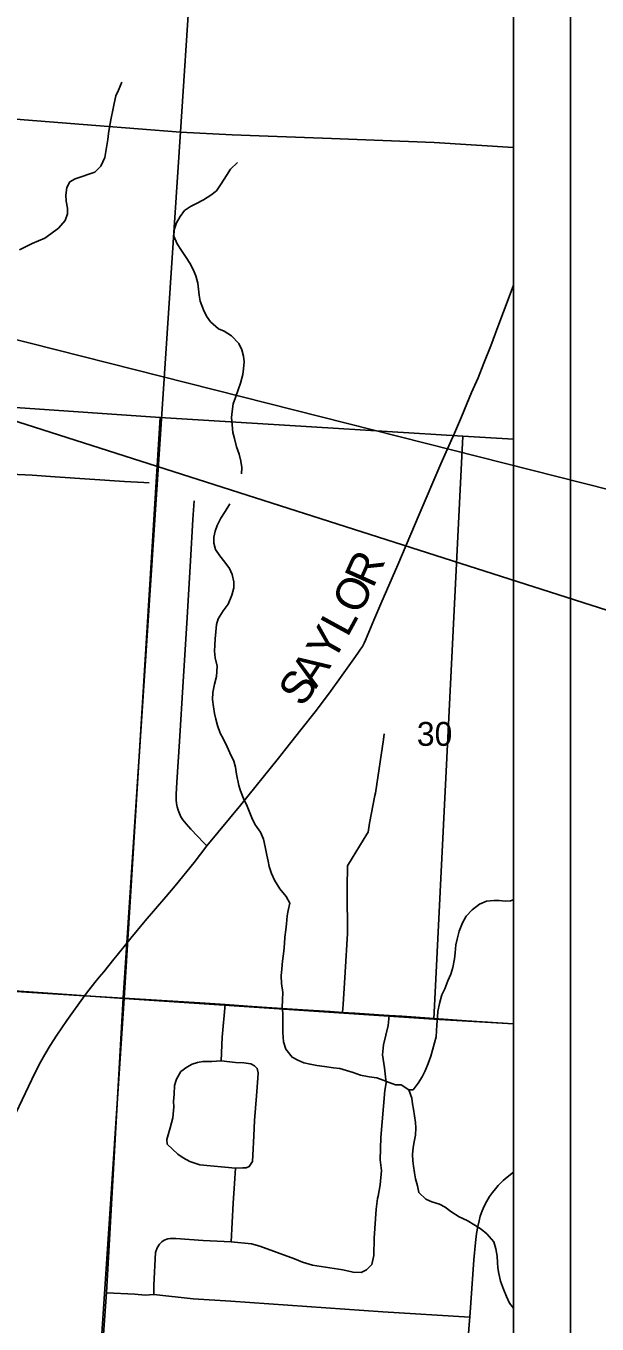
# Model space of a CAD drawing. Extents: x 0 to 34, y 0 to 22.
# Drawn here: x 8.044 to 9.046, y 15.327 to 17.603 of the extents above; entities that cross this region are included whole.
import ezdxf

# ---------------------------------------------------------------- set-up
doc = ezdxf.new("R2010")
doc.units = 0
for name, color, linetype in [('GM_X_Corporation', 7, 'Continuous'), ('GM_X_County_Road', 7, 'Continuous'), ('GM_X_Minor_River', 7, 'Continuous'), ('GM_X_Section_Text', 7, 'Continuous'), ('GM_X_State_Route', 7, 'Continuous'), ('GM_X_Township_Road', 7, 'Continuous'), ('GM_X_Township_Road_Text', 7, 'Continuous'), ('SH_Data', 7, 'Continuous'), ('SH_Text', 7, 'Continuous')]:
    doc.layers.add(name, color=color, linetype=linetype)

msp = doc.modelspace()

# ---------------------------------------------------------------- linework, layer by layer
at = {"layer": 'GM_X_Corporation'}
for points in [[(3.0167, 14.1), (8.9, 14.1), (8.9, 17.9001), (8.3494, 17.9349), (8.1742, 17.9461), (7.8447, 17.9665), (7.5344, 17.9901), (7.2487, 18.0119), (6.5673, 18.064), (6.0904, 18.0983)], [(3.0167, 14.1), (8.1011, 14.1), (8.1079, 14.1976), (8.1194, 14.3701), (8.12, 14.3767), (8.1177, 14.3813), (8.1477, 14.8503), (8.1489, 14.8684), (8.1501, 14.8865), (8.1855, 15.3822), (8.215, 15.8988), (8.2214, 15.9952), (8.3153, 17.4178), (8.3494, 17.9349), (8.1742, 17.9461), (7.8447, 17.9665), (7.5344, 17.9901), (7.2487, 18.0119), (6.5673, 18.064), (6.0904, 18.0983)], [(3.0169, 14.1), (8.9, 14.1), (8.9, 17.8995), (8.3496, 17.9344), (8.1744, 17.9455), (7.8449, 17.9659), (7.5346, 17.9896), (7.2489, 18.0114), (6.5646, 18.0583), (6.0906, 18.0978)]]:
    msp.add_lwpolyline(points, dxfattribs=at)
for points in [[(8.1011, 14.1), (8.9, 14.1), (8.9, 17.9001), (8.3494, 17.9349), (8.3153, 17.4178), (8.2214, 15.9952), (8.215, 15.8988), (8.1855, 15.3822), (8.1501, 14.8865), (8.1489, 14.8684), (8.1477, 14.8503), (8.1177, 14.3813), (8.12, 14.3767), (8.1194, 14.3701), (8.1079, 14.1976)], [(7.7715, 16.9516), (8.2797, 16.9169), (8.2166, 15.8976), (7.7055, 15.9334)], [(8.2797, 16.9169), (8.811, 16.8838), (8.7597, 15.8616), (8.2166, 15.8976)], [(8.9, 15.8531), (8.9, 16.8787), (8.811, 16.8838), (8.7597, 15.8616)], [(7.2018, 15.9686), (7.7055, 15.9334), (8.2166, 15.8976), (8.1497, 14.8881), (7.1441, 14.9641)], [(8.9, 14.8153), (8.9, 15.8531), (8.7597, 15.8616), (8.2166, 15.8976), (8.1497, 14.8881), (8.1482, 14.8695)]]:
    msp.add_lwpolyline(points, close=True, dxfattribs=at)
at = {"layer": 'GM_X_County_Road'}
for points in [[(6.5533, 16.0128), (6.5873, 16.0106), (7.3781, 15.9549), (7.4292, 15.951), (7.4581, 15.95), (7.5317, 15.9445), (7.5902, 15.9401), (7.7101, 15.9317), (7.717, 15.9313), (7.7697, 15.9277), (7.8593, 15.9217), (7.9306, 15.9171), (7.9832, 15.9128), (8.0451, 15.9087), (8.1468, 15.9026)], [(8.1468, 15.9026), (8.2152, 15.8983), (8.2261, 15.8976)], [(8.2261, 15.8976), (8.3589, 15.8893), (8.394, 15.887), (8.4333, 15.8844), (8.4581, 15.8826), (8.5293, 15.8777), (8.5781, 15.8746), (8.5998, 15.8732), (8.6214, 15.8718), (8.6725, 15.8685), (8.6816, 15.8679), (8.7037, 15.8664), (8.8175, 15.8587), (8.9, 15.8531)], [(8.819, 15.2872), (8.8226, 15.3327), (8.823, 15.3387), (8.8304, 15.439), (8.8332, 15.4699), (8.8351, 15.4854), (8.8371, 15.4977), (8.8393, 15.5076), (8.8415, 15.516), (8.8448, 15.5252), (8.8483, 15.5335), (8.8527, 15.5419), (8.8577, 15.5501), (8.8629, 15.5576), (8.868, 15.5641), (8.8727, 15.5696), (8.877, 15.574), (8.8817, 15.5784), (8.8888, 15.5845), (8.9, 15.5929)]]:
    msp.add_lwpolyline(points, dxfattribs=at)
at = {"layer": 'GM_X_Minor_River'}
for points in [[(8.1431, 17.3395), (8.1545, 17.3432), (8.1652, 17.3472), (8.1759, 17.3577), (8.1825, 17.3725), (8.1849, 17.3869), (8.1878, 17.4043), (8.189, 17.4149), (8.1918, 17.4297), (8.1938, 17.4414), (8.1966, 17.4558), (8.1994, 17.4676), (8.2022, 17.4808), (8.2065, 17.491), (8.2123, 17.505)], [(8.4157, 17.364), (8.4035, 17.3523), (8.3962, 17.3414), (8.3869, 17.3263), (8.3785, 17.3143), (8.3689, 17.3068), (8.3556, 17.2982), (8.3434, 17.2918), (8.3331, 17.287), (8.3228, 17.2795), (8.3151, 17.269), (8.3082, 17.258), (8.3042, 17.2456), (8.3037, 17.2349), (8.3097, 17.2212), (8.3175, 17.2094), (8.3253, 17.1975), (8.332, 17.1872), (8.338, 17.1765), (8.3424, 17.1651), (8.3457, 17.1521), (8.3471, 17.1415), (8.3485, 17.1312), (8.3502, 17.121), (8.3558, 17.1053), (8.3613, 17.0943), (8.3684, 17.0847), (8.3823, 17.0724), (8.3921, 17.0681), (8.4049, 17.06), (8.4176, 17.0462), (8.4232, 17.0355), (8.4261, 17.0245), (8.4271, 17.0143), (8.4262, 17.0021), (8.4246, 16.9919), (8.4207, 16.9767), (8.4167, 16.965), (8.4121, 16.9518), (8.4081, 16.9404), (8.4061, 16.9272), (8.4052, 16.9169), (8.4062, 16.904), (8.4076, 16.8903), (8.4102, 16.8801), (8.4138, 16.8652), (8.4186, 16.8523), (8.4211, 16.8401), (8.4229, 16.8287), (8.4224, 16.8177)], [(8.033, 17.2108), (8.0456, 17.2171), (8.0555, 17.222), (8.0665, 17.2268), (8.0772, 17.2312), (8.0882, 17.2387), (8.1016, 17.2488), (8.1131, 17.262), (8.1174, 17.2737), (8.1175, 17.2836), (8.115, 17.2961), (8.1143, 17.3068), (8.116, 17.32), (8.1214, 17.3298), (8.1309, 17.335), (8.1431, 17.3395)], [(8.5547, 15.7801), (8.543, 15.7822), (8.5321, 15.7849), (8.5211, 15.7892), (8.5113, 15.7946), (8.5005, 15.8088), (8.4961, 15.8217), (8.4948, 15.8381), (8.495, 15.8612), (8.4948, 15.8722), (8.4941, 15.8817), (8.4946, 15.8954), (8.4948, 15.9083), (8.4927, 15.9239), (8.492, 15.9375), (8.4933, 15.9497), (8.4946, 15.9629), (8.4967, 15.9808), (8.498, 15.9944), (8.4985, 16.005), (8.5001, 16.0183), (8.5014, 16.0289), (8.5026, 16.0426), (8.5043, 16.052), (8.5074, 16.0649), (8.5007, 16.0767), (8.4899, 16.0898), (8.4802, 16.105), (8.475, 16.1169), (8.471, 16.1291), (8.4692, 16.1386), (8.4667, 16.1492), (8.4638, 16.1637), (8.4609, 16.177), (8.4557, 16.1892), (8.4472, 16.2018), (8.442, 16.2117), (8.4372, 16.2231), (8.4324, 16.235), (8.4261, 16.2487), (8.4205, 16.2617), (8.4176, 16.2712), (8.414, 16.2909), (8.4119, 16.3031), (8.409, 16.3138), (8.4023, 16.3286), (8.3975, 16.3389), (8.3901, 16.3534), (8.3853, 16.363), (8.3805, 16.3763), (8.3776, 16.3877), (8.3754, 16.3976), (8.3736, 16.409), (8.3719, 16.422), (8.372, 16.4345), (8.3752, 16.4489), (8.3784, 16.4625), (8.3801, 16.4807), (8.3765, 16.4952), (8.3754, 16.5069), (8.3756, 16.5176), (8.3764, 16.5282), (8.3773, 16.5407), (8.3786, 16.5536), (8.3814, 16.5638), (8.3902, 16.5774), (8.3991, 16.589), (8.4057, 16.6053), (8.4088, 16.6178), (8.409, 16.6284), (8.4064, 16.6414), (8.4012, 16.6517), (8.3934, 16.6627), (8.3844, 16.6738), (8.377, 16.6849), (8.3741, 16.6963), (8.3742, 16.707), (8.3762, 16.7172), (8.3801, 16.727), (8.3863, 16.7399), (8.3936, 16.7516), (8.4021, 16.7655)], [(8.716, 15.7375), (8.7236, 15.7374), (8.7325, 15.7491), (8.7394, 15.76), (8.7448, 15.7706), (8.7503, 15.7834), (8.7549, 15.7963), (8.7577, 15.8069), (8.7613, 15.8197), (8.764, 15.8303), (8.7649, 15.841), (8.7654, 15.8516), (8.7663, 15.8649), (8.7672, 15.8747), (8.77, 15.8891), (8.7743, 15.9042), (8.779, 15.9148), (8.7848, 15.9288), (8.7898, 15.9401), (8.7934, 15.9522), (8.7962, 15.9674), (8.7974, 15.978), (8.7987, 15.9917), (8.8007, 16.0019), (8.8047, 16.0159), (8.8105, 16.0302), (8.8167, 16.042), (8.8274, 16.0532), (8.84, 16.0633), (8.8526, 16.0685), (8.8651, 16.0695), (8.8746, 16.0698), (8.8852, 16.0686), (8.8946, 16.0688), (8.9, 16.0708)], [(8.9, 15.3543), (8.8927, 15.3633), (8.8872, 15.3751), (8.8824, 15.3881), (8.8772, 15.4018), (8.874, 15.4155), (8.8725, 15.425), (8.8719, 15.4349), (8.8709, 15.4455), (8.8687, 15.4588), (8.8655, 15.4706), (8.8527, 15.4848), (8.843, 15.4933), (8.8321, 15.5002), (8.8185, 15.5083), (8.8042, 15.5145), (8.7899, 15.5242), (8.7797, 15.5319), (8.77, 15.5369), (8.7567, 15.5412), (8.7462, 15.5459), (8.7334, 15.5574), (8.7313, 15.5692), (8.7276, 15.5814), (8.7258, 15.592), (8.7241, 15.6034), (8.723, 15.6129), (8.7228, 15.6239), (8.7237, 15.6361), (8.7253, 15.6463), (8.7281, 15.6577), (8.7282, 15.6706), (8.7276, 15.6804), (8.7258, 15.6918), (8.7244, 15.7036), (8.7226, 15.7131), (8.7216, 15.723), (8.716, 15.7375), (8.7029, 15.746), (8.693, 15.7464), (8.6817, 15.7504), (8.6708, 15.7543), (8.6598, 15.7586), (8.6466, 15.7602), (8.6311, 15.763), (8.6183, 15.7681), (8.6066, 15.7716), (8.5952, 15.7748), (8.5839, 15.776), (8.568, 15.7781), (8.5547, 15.7801)]]:
    msp.add_lwpolyline(points, dxfattribs=at)
at = {"layer": 'GM_X_State_Route'}
msp.add_lwpolyline([(7.8165, 17.456), (7.9224, 17.4479), (8.1671, 17.4291), (8.3155, 17.4173), (8.4063, 17.4124), (8.5807, 17.4058), (8.7608, 17.3992), (8.8999, 17.39), (8.9, 17.39)], dxfattribs=at)
at = {"layer": 'GM_X_Township_Road'}
for points in [[(8.9, 17.149), (8.8921, 17.1282), (8.8723, 17.0758), (8.8598, 17.0424), (8.8477, 17.0117), (8.8376, 16.9861), (8.8263, 16.9606), (8.8178, 16.9406), (8.8083, 16.9177), (8.796, 16.8892), (8.7884, 16.8722), (8.7725, 16.8352), (8.7344, 16.7468), (8.6968, 16.6583), (8.6671, 16.59), (8.655, 16.5614), (8.6433, 16.5333), (8.6403, 16.5262), (8.6379, 16.5209), (8.6349, 16.5153), (8.6314, 16.5102), (8.6266, 16.5035), (8.6197, 16.4932), (8.5962, 16.4607), (8.5772, 16.4339), (8.5519, 16.4002), (8.5268, 16.3689), (8.5001, 16.3354), (8.4872, 16.3192), (8.4214, 16.2373), (8.3618, 16.1653), (8.3392, 16.136), (8.306, 16.095), (8.2896, 16.0758), (8.2719, 16.0547), (8.2536, 16.0336), (8.2286, 16.0032)], [(8.0181, 16.8175), (8.0555, 16.8155), (8.0958, 16.8126), (8.217, 16.8046), (8.2512, 16.8026), (8.2605, 16.8019)], [(8.3618, 16.1653), (8.3562, 16.1704), (8.3334, 16.1944), (8.3252, 16.2038), (8.3196, 16.2113), (8.3163, 16.2165), (8.3135, 16.2221), (8.3112, 16.2278), (8.3095, 16.2338), (8.3083, 16.2399), (8.3079, 16.2461), (8.3079, 16.2553), (8.309, 16.277), (8.3138, 16.3483), (8.32, 16.4537), (8.3266, 16.5561), (8.3331, 16.6655), (8.3373, 16.7378), (8.3397, 16.7704)], [(8.5998, 15.8732), (8.6011, 15.8872), (8.6044, 15.9441), (8.6086, 16.0119), (8.6077, 16.0861), (8.6079, 16.0965), (8.6084, 16.1262), (8.6085, 16.1305), (8.6165, 16.1438), (8.6424, 16.1861), (8.6445, 16.1895), (8.6474, 16.2051), (8.6566, 16.2538), (8.6574, 16.2579), (8.6597, 16.2734), (8.6714, 16.3518), (8.6729, 16.3617)], [(8.2286, 16.0032), (8.2216, 15.9946), (8.2044, 15.9735), (8.1983, 15.9664), (8.181, 15.9445), (8.1729, 15.9351), (8.165, 15.9256), (8.1545, 15.9123), (8.1468, 15.9026)], [(8.1468, 15.9026), (8.1158, 15.8593), (8.0985, 15.8336), (8.0869, 15.8153), (8.0774, 15.7994), (8.07, 15.7858), (8.0602, 15.7664), (8.0266, 15.6966), (8.0147, 15.6714), (7.999, 15.6376), (7.956, 15.5482), (7.9359, 15.5063), (7.9115, 15.4562), (7.8839, 15.4007), (7.8417, 15.3177)], [(8.4045, 15.471), (8.4081, 15.5389), (8.4102, 15.5732), (8.412, 15.6002), (8.3492, 15.6062), (8.3317, 15.6117), (8.3204, 15.6182), (8.311, 15.6248), (8.2919, 15.6423), (8.2913, 15.6502), (8.2976, 15.6706), (8.3023, 15.6884), (8.3039, 15.7078), (8.3031, 15.7168), (8.3041, 15.7296), (8.3047, 15.7449), (8.3082, 15.7564), (8.3162, 15.7694), (8.3264, 15.7771), (8.3361, 15.7827), (8.3454, 15.7854), (8.3545, 15.787), (8.3706, 15.7873), (8.3867, 15.7883), (8.3885, 15.8297), (8.394, 15.887)], [(8.6621, 15.5509), (8.6661, 15.5709), (8.6683, 15.5957), (8.6661, 15.6147), (8.667, 15.6537), (8.6738, 15.7363), (8.6765, 15.75), (8.6732, 15.7758), (8.6702, 15.7989), (8.6717, 15.8161), (8.6796, 15.8502), (8.6816, 15.8679)], [(8.412, 15.6002), (8.4251, 15.6004), (8.4309, 15.6009), (8.4361, 15.6028), (8.4416, 15.6119), (8.4424, 15.6227), (8.4442, 15.6565), (8.4453, 15.6837), (8.449, 15.7267), (8.4514, 15.7579), (8.4517, 15.7674), (8.4503, 15.7749), (8.4455, 15.7798), (8.4391, 15.7828), (8.4268, 15.7847), (8.412, 15.7855), (8.3867, 15.7883)], [(8.269, 15.3786), (8.269, 15.395), (8.2719, 15.452), (8.2747, 15.4601), (8.2788, 15.4667), (8.2825, 15.4708), (8.2866, 15.4736), (8.2931, 15.4759), (8.2979, 15.4768), (8.3076, 15.4768), (8.355, 15.4734), (8.4045, 15.471), (8.4398, 15.4671), (8.4547, 15.4634), (8.5155, 15.4409), (8.5296, 15.4352), (8.5469, 15.4302), (8.6005, 15.4215), (8.6183, 15.4175), (8.6322, 15.4173), (8.6417, 15.4219), (8.651, 15.4312), (8.6546, 15.4467), (8.6555, 15.4773), (8.659, 15.5279), (8.6612, 15.5469), (8.6621, 15.5509)], [(8.823, 15.3387), (8.6705, 15.3483), (8.4036, 15.367), (8.3376, 15.3711), (8.269, 15.3786), (8.2533, 15.3776), (8.2353, 15.3788), (8.1857, 15.3817)]]:
    msp.add_lwpolyline(points, dxfattribs=at)
at = {"layer": 'SH_Data'}
for p, q in [((9, 21), (9, 14)), ((8.9, 20.9), (8.9, 14.1))]:
    msp.add_line(p, q, dxfattribs=at)
at = {"layer": 'SH_Text'}
msp.add_lwpolyline([(9.625, 16.6492), (9.625, 16.3992), (5.875, 17.598)], close=True, dxfattribs=at)

# ---------------------------------------------------------------- texts
at = {"layer": 'GM_X_Section_Text'}
msp.add_text('30', height=0.04186, rotation=0, dxfattribs=at).set_placement((8.7302, 16.3408))
at = {"layer": 'GM_X_Township_Road_Text'}
for s, rotation, p in [('R', 65.8019, (8.6534, 16.6158)), ('O', 63.1676, (8.6297, 16.5687)), ('Y', 60.3824, (8.5831, 16.4852)), ('L', 61.3555, (8.6084, 16.5296)), ('A', 56.3143, (8.5531, 16.4399)), ('S', 54.0177, (8.5292, 16.4068))]:
    msp.add_text(s, height=0.0568, rotation=rotation, dxfattribs=at).set_placement(p)

doc.saveas('drawing.dxf')
